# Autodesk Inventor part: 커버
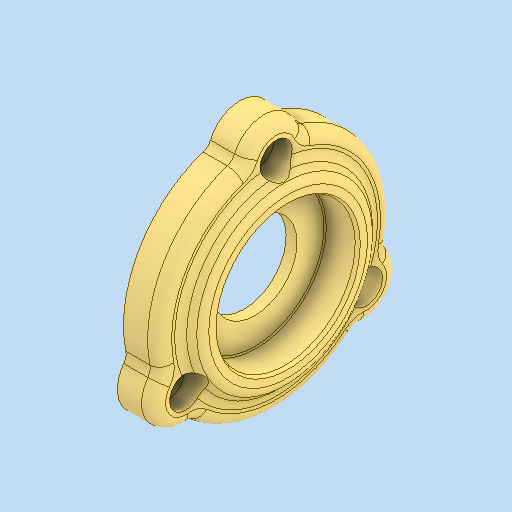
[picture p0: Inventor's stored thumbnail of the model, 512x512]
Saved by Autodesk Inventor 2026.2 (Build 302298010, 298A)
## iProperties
Created: 2026-03
Part Number: 커버
Material: 알루미늄 6061
Document SubType Name: Modeling
Designer: PC-2-03
Density: 2.7 g/cm^3
Appearance: 기본값
Author: jhkim
Sending System: Autodesk Inventor 2026
Preprocessor: ST-DEVELOPER v20.1
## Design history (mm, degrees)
feature "솔리드1"
node "솔리드2"
